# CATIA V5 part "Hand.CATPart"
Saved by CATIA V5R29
Part number: Hand
Source: Unknown
Bounding box of the stored display mesh (mm): x 0 to 80, y 20.231 to 271.175, z -18.071 to 66.93
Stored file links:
  C:\가치같이\SmartFactory_BoxErectorConveyor\Boxing(over)\Hand.CATPart
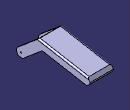
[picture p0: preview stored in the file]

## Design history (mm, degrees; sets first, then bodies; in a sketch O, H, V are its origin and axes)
Body1 (main body)
  Solid1 "PartBody": solid without history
